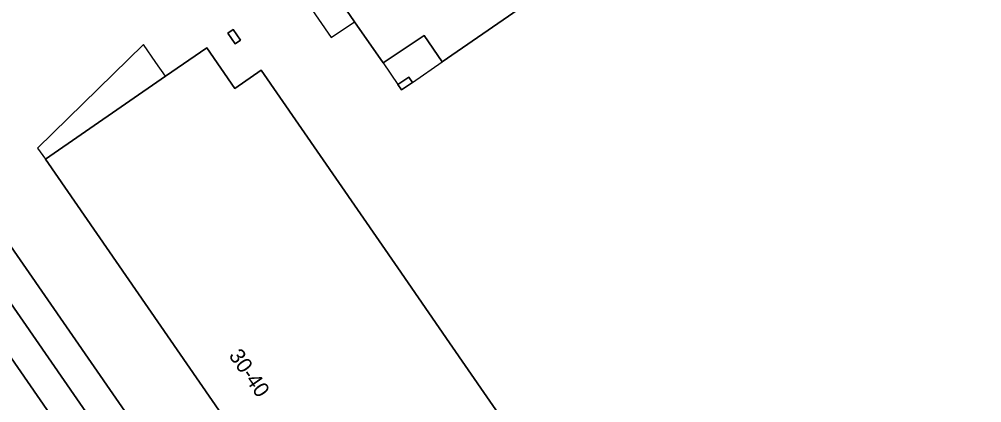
# Model space of a CAD drawing. Extents: x 157445 to 158888, y 383061 to 384688.
# Drawn here: x 157918.7 to 157981.3, y 383348.6 to 383373.5 of the extents above; entities that cross this region are included whole.
import ezdxf

# ---------------------------------------------------------------- set-up
doc = ezdxf.new("R2010")
doc.units = 0
for name, color, linetype in [('IMGEO_Erf', 7, 'Continuous'), ('IMGEO_Pand', 7, 'Continuous'), ('IMGEO_Pand_nummerreeks', 7, 'Continuous'), ('IMGEO_Pand_overbouw', 7, 'Continuous'), ('IMGEO_Parkeervlak_open', 7, 'Continuous'), ('IMGEO_Rijbaan_lokaal_open', 7, 'Continuous'), ('IMGEO_Voetpad_open', 7, 'Continuous')]:
    doc.layers.add(name, color=color, linetype=linetype)

msp = doc.modelspace()

# ---------------------------------------------------------------- linework, layer by layer
at = {"layer": 'IMGEO_Erf'}
msp.add_lwpolyline([(157867.433, 383432.258), (157908.666, 383372.402), (157939.64, 383327.608), (157940.949, 383325.715), (157950.145, 383325.96), (157966.252, 383337.038), (157969.609, 383339.347), (158000, 383360.249), (158003.024, 383362.329), (158006.393, 383364.646), (158017.962, 383372.552), (158018.659, 383373.03), (158024.393, 383376.961), (158024.278, 383377.131)], dxfattribs=at)
for points in [[(157972.05, 383404.463), (157976.409, 383398.151), (157978.273, 383395.453), (157975.63, 383393.585), (157976.812, 383391.873), (157963.966, 383383.005), (157959.083, 383379.635), (157946.205, 383370.745), (157945.02, 383372.454), (157942.354, 383370.661), (157940.498, 383373.348), (157936.154, 383379.662)], [(157933.083, 383372.137), (157932.737, 383371.899), (157932.254, 383372.599), (157932.6, 383372.837)], [(157930.882, 383371.648), (157932.707, 383368.999), (157934.428, 383370.184), (157943.305, 383357.333), (157946.676, 383352.453), (157955.361, 383339.866), (157950.942, 383336.831), (157943.141, 383331.454), (157920.388, 383364.411), (157928.195, 383369.805)], [(157944.262, 383369.398), (157943.561, 383368.915), (157943.322, 383369.263), (157944.024, 383369.745)]]:
    msp.add_lwpolyline(points, close=True, dxfattribs=at)
at = {"layer": 'IMGEO_Pand'}
for points in [[(157942.354, 383370.661), (157945.02, 383372.454), (157946.205, 383370.745), (157959.083, 383379.635), (157963.966, 383383.005), (157976.812, 383391.873), (157975.63, 383393.585), (157978.273, 383395.453), (157976.409, 383398.151), (157972.05, 383404.463), (157936.154, 383379.662), (157940.498, 383373.348)], [(157933.083, 383372.137), (157932.6, 383372.837), (157932.254, 383372.599), (157932.737, 383371.899)], [(157928.195, 383369.805), (157920.388, 383364.411), (157943.141, 383331.454), (157950.942, 383336.831), (157955.361, 383339.866), (157946.676, 383352.453), (157943.305, 383357.333), (157934.428, 383370.184), (157932.707, 383368.999), (157930.882, 383371.648)], [(157944.262, 383369.398), (157944.024, 383369.745), (157943.322, 383369.263), (157943.561, 383368.915)]]:
    msp.add_lwpolyline(points, close=True, dxfattribs=at)
at = {"layer": 'IMGEO_Pand_overbouw'}
for points in [[(157940.498, 383373.348), (157936.154, 383379.662), (157934.624, 383378.662), (157938.98, 383372.315)], [(157944.262, 383369.398), (157946.205, 383370.745), (157945.02, 383372.454), (157942.354, 383370.661), (157943.322, 383369.263), (157944.024, 383369.745)], [(157928.195, 383369.805), (157927.576, 383370.695), (157926.763, 383371.866), (157920.871, 383366.088), (157919.879, 383365.116), (157920.388, 383364.411)]]:
    msp.add_lwpolyline(points, close=True, dxfattribs=at)
at = {"layer": 'IMGEO_Parkeervlak_open'}
for points in [[(157863.215, 383431.182), (157863.862, 383430.224), (157871.979, 383418.406), (157880.805, 383405.562), (157894.321, 383385.972), (157905.565, 383369.639), (157915.623, 383355.122), (157935.388, 383326.53), (157935.643, 383326.174), (157936.465, 383325.145)], [(157936.153, 383328.952), (157907.044, 383371.058), (157890.489, 383394.989), (157884.813, 383403.235), (157866.622, 383429.736)]]:
    msp.add_lwpolyline(points, dxfattribs=at)
at = {"layer": 'IMGEO_Rijbaan_lokaal_open'}
msp.add_lwpolyline([(157876.859, 383399.812), (157883.617, 383389.989), (157889.899, 383380.858), (157890.097, 383380.63), (157892.494, 383377.128), (157897.603, 383369.765), (157899.471, 383367.034), (157900.174, 383366.038), (157907.035, 383356.127), (157911.123, 383350.155), (157911.832, 383349.127), (157917.679, 383340.677), (157921.646, 383334.932), (157926.89, 383327.295), (157930.145, 383322.573), (157930.847, 383321.656), (157936.465, 383325.145), (157935.643, 383326.174), (157935.388, 383326.53), (157915.623, 383355.122), (157905.565, 383369.639), (157894.321, 383385.972), (157880.805, 383405.562)], dxfattribs=at)
at = {"layer": 'IMGEO_Voetpad_open'}
for points in [[(157866.622, 383429.736), (157884.813, 383403.235), (157885.67, 383403.825), (157891.346, 383395.579), (157890.489, 383394.989), (157907.044, 383371.058), (157936.153, 383328.952)], [(157936.465, 383325.145), (157939.64, 383327.608), (157908.666, 383372.402)]]:
    msp.add_lwpolyline(points, dxfattribs=at)

# ---------------------------------------------------------------- texts
at = {"layer": 'IMGEO_Pand_nummerreeks'}
msp.add_text('30-40', height=1, rotation=304.6206, dxfattribs=at).set_placement((157932.28, 383351.621))

doc.saveas('drawing.dxf')
